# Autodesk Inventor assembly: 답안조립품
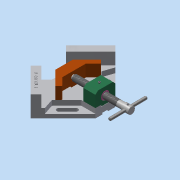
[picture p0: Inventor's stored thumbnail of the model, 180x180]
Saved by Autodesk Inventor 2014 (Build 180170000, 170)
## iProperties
Created: 2019-04
Part Number: 답안조립품
Document SubType Name: Assembly
Designer: 601-06
Author: 601-06
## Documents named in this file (11)
- C:\Users\601-06\Desktop\490408V1005\답안조립품.iam
- C:\Users\601-06\Desktop\490408V1005\베이스.ipt
- C:\Users\601-06\Desktop\490408V1005\리드스크류.ipt
- C:\Users\601-06\Desktop\490408V1005\멈춤나사 M4x5.ipt
- C:\Users\601-06\Desktop\490408V1005\멈춤나사 M4x10.ipt
- C:\Users\601-06\Desktop\490408V1005\볼트 M4x16.ipt
- C:\Users\601-06\Desktop\490408V1005\부시.ipt
- C:\Users\601-06\Desktop\490408V1005\서포트.ipt
- C:\Users\601-06\Desktop\490408V1005\조.ipt
- C:\Users\601-06\Desktop\490408V1005\평행 핀 2.5x24.ipt
- C:\Users\601-06\Desktop\490408V1005\핸들.ipt
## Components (1 placed, 1 different names)
1. 핸들:1
